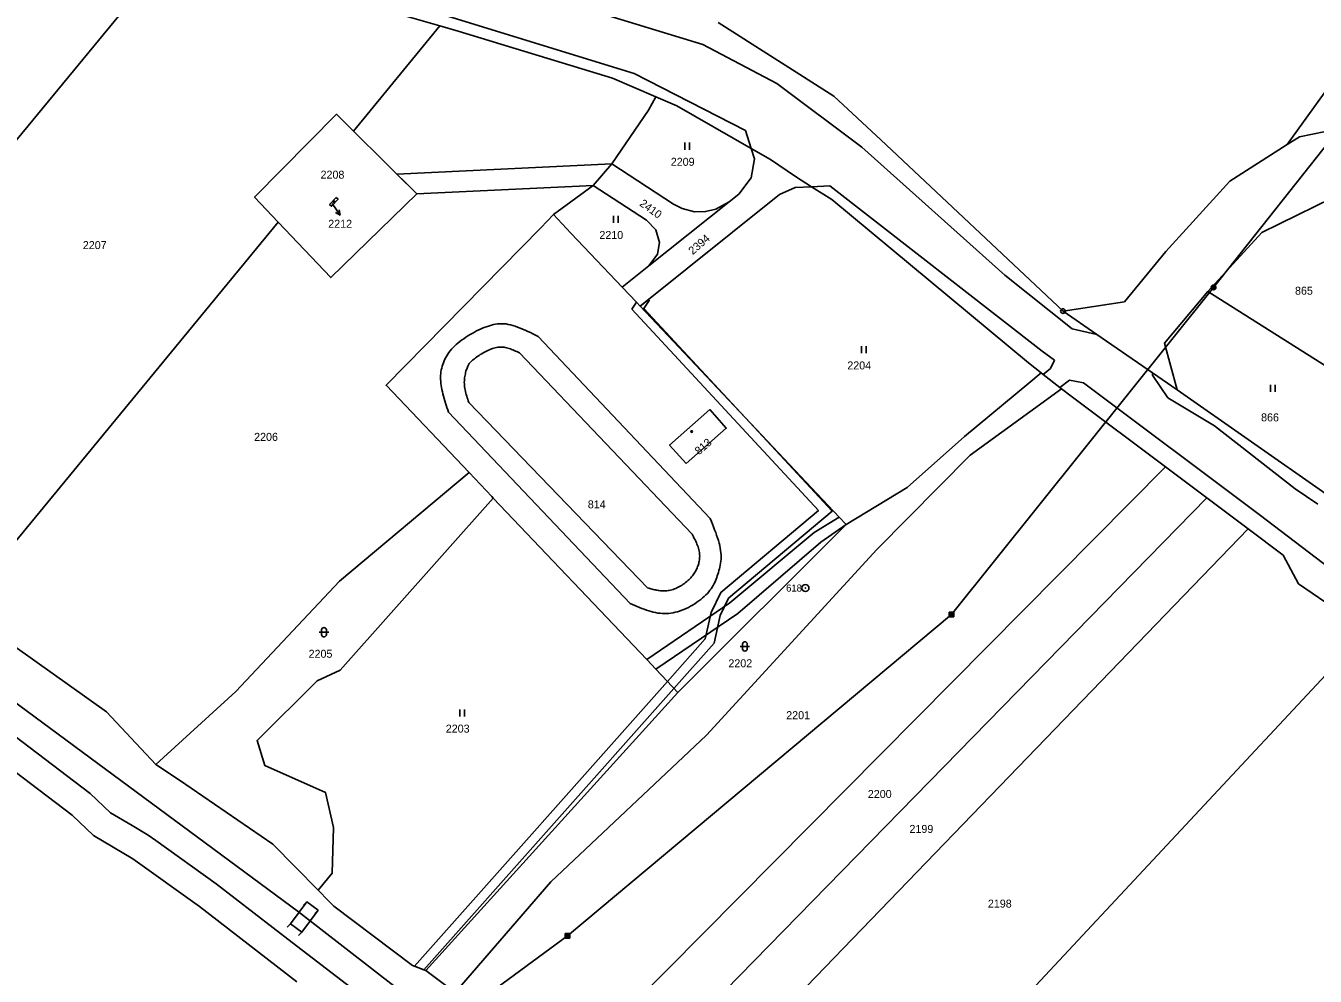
# Model space of a CAD drawing. Extents: x -504988 to -494607, y -1123820 to -1114018.
# Drawn here: x -503013.9 to -502739.9, y -1120138.9 to -1119937 of the extents above; entities that cross this region are included whole.
import ezdxf

# ---------------------------------------------------------------- set-up
doc = ezdxf.new("R2010")
doc.units = 0
for name, color, linetype in [('Hranice parcel', 7, 'Continuous'), ('Parcelní čísla', 7, 'Continuous'), ('Pop  PČ popisy', 7, 'Continuous'), ('Poz předměty', 7, 'Continuous'), ('Vnitřní kresba', 7, 'Continuous'), ('Věcná břemena k části', 7, 'Continuous'), ('Značky bodu BP', 7, 'Continuous'), ('Značky budov', 7, 'Continuous'), ('Značky kultur', 7, 'Continuous')]:
    doc.layers.add(name, color=color, linetype=linetype)

msp = doc.modelspace()

# ---------------------------------------------------------------- linework, layer by layer
at = {"layer": 'Hranice parcel'}
for p, q in [((-502981.99, -1119920.09), (-503071.71, -1120028.97)), ((-502925.9, -1119937.02), (-502944.29, -1119959.35)), ((-502893.32, -1119970.88), (-502889.37, -1119966.29)), ((-502901.73, -1119977.1), (-502893.32, -1119970.88)), ((-502864.44, -1119974.35), (-502881.5, -1119987.99)), ((-502960.25, -1119978.71), (-503027.8, -1120060.7)), ((-502887.17, -1119992.52), (-502881.5, -1119987.99)), ((-502762.74, -1119993.42), (-502729.28, -1120014.6)), ((-502769.23, -1120014.3), (-502737.68, -1120036.4)), ((-502771.74, -1120030.66), (-502900.98, -1120161.07)), ((-502762.94, -1120037.27), (-502771.74, -1120030.66)), ((-502762.94, -1120037.27), (-502892.07, -1120169.28)), ((-502754.13, -1120043.86), (-502883.26, -1120177.59)), ((-502728.91, -1120065.44), (-502856.99, -1120202.68)), ((-502875.32, -1120078.64), (-502928.87, -1120137.7)), ((-502928.87, -1120137.7), (-502922.69, -1120142.32))]:
    msp.add_line(p, q, dxfattribs=at)
for points in [[(-502745.87, -1119962.2), (-502726.12, -1119934.81), (-502725.62, -1119934.02), (-502724.98, -1119932.56), (-502724.62, -1119930.83), (-502724.51, -1119929.79), (-502723.39, -1119925.27), (-502721.48, -1119921.82), (-502719.31, -1119919.3), (-502694.18, -1119895.38), (-502669.78, -1119860.67), (-502662.28, -1119848.04), (-502656.73, -1119834.18), (-502653.41, -1119819.67), (-502652.38, -1119805.25), (-502653.63, -1119790.28), (-502657.45, -1119766.86), (-502661.64, -1119750.43), (-502684.82, -1119684.46), (-502688.04, -1119676.45), (-502695.69, -1119659.69), (-502696.84, -1119656.32)], [(-502925.9, -1119937.02), (-502942.28, -1119932.34), (-502981.04, -1119920.39), (-502981.99, -1119920.09)], [(-502866.76, -1119936.27), (-502842.16, -1119951.9), (-502832.22, -1119961.21), (-502793.5, -1119997.58)], [(-502880.05, -1119952.05), (-502889.25, -1119948.14), (-502921.99, -1119938.14), (-502925.9, -1119937.02)], [(-502889.37, -1119966.29), (-502881.58, -1119954.91), (-502880.05, -1119952.05)], [(-502859.74, -1119963.02), (-502875.54, -1119953.97), (-502880.05, -1119952.05)], [(-502960.25, -1119978.71), (-502965.29, -1119973.4), (-502947.89, -1119955.79), (-502944.29, -1119959.35)], [(-502734.16, -1119958.79), (-502734.97, -1119958.87), (-502743.27, -1119960.54), (-502745.87, -1119962.2)], [(-502944.29, -1119959.35), (-502930.79, -1119972.7), (-502949.08, -1119990.48), (-502960.25, -1119978.71)], [(-502864.44, -1119974.35), (-502862.41, -1119972.72), (-502859.78, -1119969.29), (-502859.04, -1119965.26), (-502859.74, -1119963.02)], [(-502859.74, -1119963.02), (-502855.64, -1119965.37), (-502850.31, -1119968.98), (-502846.92, -1119971.16)], [(-502745.87, -1119962.2), (-502758.03, -1119969.98), (-502771.67, -1119984.9), (-502780.46, -1119995.59), (-502793.5, -1119997.58)], [(-502889.37, -1119966.29), (-502876.25, -1119974.84), (-502874.45, -1119975.8), (-502871.8, -1119976.47), (-502869.43, -1119976.46), (-502867.25, -1119975.93), (-502864.44, -1119974.35)], [(-502881.5, -1119987.99), (-502879.69, -1119985.48), (-502879.26, -1119983.01), (-502880.04, -1119980.35), (-502881.97, -1119978.27), (-502893.32, -1119970.88)], [(-502846.92, -1119971.16), (-502850.4, -1119971.34), (-502853.76, -1119972.85), (-502883.38, -1119996.53)], [(-502798.12, -1120010.71), (-502800.84, -1120008.56), (-502842.65, -1119973.89), (-502846.92, -1119971.16)], [(-502762.74, -1119993.42), (-502751.25, -1119980.9), (-502736.26, -1119973.51), (-502722.85, -1119971.39)], [(-502947.95, -1119973.44), (-502947.53, -1119973.83), (-502948.91, -1119975.31), (-502949.33, -1119974.92), (-502947.95, -1119973.44)], [(-502901.73, -1119977.1), (-502904.47, -1119979.89), (-502937.32, -1120013.35), (-502919.69, -1120031.91)], [(-502887.17, -1119992.52), (-502888.43, -1119991.19), (-502898.05, -1119981.01), (-502901.73, -1119977.1)], [(-503153.21, -1119984.84), (-503117.67, -1120013.23), (-503061.37, -1120053.65), (-503000.19, -1120100.11), (-502995.88, -1120104.15), (-502991.31, -1120106.89), (-502987.9, -1120108.94), (-502986.29, -1120110.08), (-502973.43, -1120119.24), (-502957.29, -1120131.75), (-502934.18, -1120149.41), (-502874.44, -1120202.44), (-502827.95, -1120247.84), (-502804.36, -1120271.45), (-502786.5, -1120288.33), (-502769.05, -1120304.16), (-502747.51, -1120326.1), (-502711.16, -1120365.44)], [(-502883.38, -1119996.53), (-502884.16, -1119995.71), (-502887.17, -1119992.52)], [(-502769.23, -1120014.3), (-502771.91, -1120004.43), (-502762.74, -1119993.42)], [(-502839.58, -1120042.91), (-502841.06, -1120041.34), (-502883.38, -1119996.53)], [(-502793.5, -1119997.58), (-502786.3, -1120002.54), (-502774.49, -1120010.68), (-502769.23, -1120014.3)], [(-502798.12, -1120010.71), (-502800.75, -1120012.9), (-502814.41, -1120024.23), (-502826.58, -1120035.08), (-502839.58, -1120042.91)], [(-502793.79, -1120014.13), (-502794.15, -1120013.85), (-502797.68, -1120011.06), (-502798.12, -1120010.71)], [(-502793.79, -1120014.13), (-502813.21, -1120028.22), (-502833.09, -1120048.23), (-502869.28, -1120087.69), (-502902.3, -1120118.85), (-502922.69, -1120142.32)], [(-502771.74, -1120030.66), (-502791.73, -1120015.67), (-502793.79, -1120014.13)], [(-502873.56, -1120030), (-502865.05, -1120022.47), (-502868.57, -1120018.5), (-502877.08, -1120026.04), (-502873.56, -1120030)], [(-502919.69, -1120031.91), (-502947.21, -1120054.98), (-502969.27, -1120078.39), (-502986.24, -1120093.88)], [(-502919.69, -1120031.91), (-502914.9, -1120036.96), (-502914.56, -1120037.32)], [(-502914.56, -1120037.32), (-502947.1, -1120073.87), (-502952, -1120076.13), (-502964.76, -1120088.85), (-502963.11, -1120094.14), (-502950.2, -1120099.89), (-502948.54, -1120107.32), (-502948.77, -1120116.97), (-502951.78, -1120120.6)], [(-502914.56, -1120037.32), (-502881.96, -1120071.64), (-502880.04, -1120073.67), (-502875.32, -1120078.64)], [(-502754.13, -1120043.86), (-502754.73, -1120043.41), (-502759.54, -1120039.82), (-502762.94, -1120037.27)], [(-502875.32, -1120078.64), (-502872.77, -1120076.1), (-502842.23, -1120045.55), (-502839.58, -1120042.91)], [(-502728.91, -1120065.44), (-502743.49, -1120055.51), (-502746.69, -1120049.46), (-502754.13, -1120043.86)], [(-503027.8, -1120060.7), (-502996.74, -1120082.72), (-502986.24, -1120093.88)], [(-502956.27, -1120140.08), (-502977.01, -1120124.06), (-502991.18, -1120113.97), (-502999.52, -1120108.97), (-503004.07, -1120104.7), (-503023.32, -1120090.08)], [(-502986.24, -1120093.88), (-502981.23, -1120097.21), (-502961.37, -1120110.87), (-502951.78, -1120120.6)], [(-502951.78, -1120120.6), (-502951.51, -1120120.87), (-502949.82, -1120122.58), (-502948.43, -1120124), (-502931.7, -1120136.63), (-502928.87, -1120137.7)]]:
    msp.add_lwpolyline(points, dxfattribs=at)
at = {"layer": 'Pop  PČ popisy'}
for p, q in [((-502948.8, -1119974.7), (-502947.12, -1119977.19)), ((-502947.12, -1119977.19), (-502948.1, -1119976.64)), ((-502947.12, -1119977.19), (-502947.27, -1119976.08))]:
    msp.add_line(p, q, dxfattribs=at)
at = {"layer": 'Poz předměty'}
for p, q in [((-502719.6, -1119939.6), (-502761.52, -1119992.57)), ((-502761.52, -1119992.57), (-502817.21, -1120062.04)), ((-503042.38, -1120061.42), (-502955.94, -1120125.2)), ((-502817.21, -1120062.04), (-502898.76, -1120130.34)), ((-502817.71, -1120061.54), (-502816.71, -1120061.54)), ((-502817.71, -1120062.54), (-502817.71, -1120061.54)), ((-502817.71, -1120061.74), (-502816.71, -1120061.74)), ((-502817.71, -1120061.94), (-502816.71, -1120061.94)), ((-502817.71, -1120062.14), (-502816.71, -1120062.14)), ((-502817.71, -1120062.34), (-502816.71, -1120062.34)), ((-502817.71, -1120062.54), (-502816.71, -1120062.54)), ((-502817.51, -1120062.54), (-502817.51, -1120061.54)), ((-502817.31, -1120062.54), (-502817.31, -1120061.54)), ((-502817.11, -1120062.54), (-502817.11, -1120061.54)), ((-502816.91, -1120062.54), (-502816.91, -1120061.54)), ((-502816.71, -1120062.54), (-502816.71, -1120061.54)), ((-502955.94, -1120125.2), (-502924.74, -1120149.39)), ((-502898.76, -1120130.34), (-502942.5, -1120162.33)), ((-502899.26, -1120129.84), (-502898.26, -1120129.84)), ((-502899.26, -1120130.84), (-502899.26, -1120129.84)), ((-502899.26, -1120130.04), (-502898.26, -1120130.04)), ((-502899.26, -1120130.24), (-502898.26, -1120130.24)), ((-502899.26, -1120130.44), (-502898.26, -1120130.44)), ((-502899.26, -1120130.64), (-502898.26, -1120130.64)), ((-502899.26, -1120130.84), (-502898.26, -1120130.84)), ((-502899.06, -1120130.84), (-502899.06, -1120129.84)), ((-502898.86, -1120130.84), (-502898.86, -1120129.84)), ((-502898.66, -1120130.84), (-502898.66, -1120129.84)), ((-502898.46, -1120130.84), (-502898.46, -1120129.84)), ((-502898.26, -1120130.84), (-502898.26, -1120129.84))]:
    msp.add_line(p, q, dxfattribs=at)
for radius in [0.5, 0.4, 0.3, 0.2, 0.1]:
    msp.add_circle((-502761.52, -1119992.57), radius, dxfattribs=at)
at = {"layer": 'Vnitřní kresba'}
for p, q in [((-502884.59, -1119947.09), (-502935.96, -1119931.25)), ((-502891.62, -1119934.38), (-502870.01, -1119940.96)), ((-502870.01, -1119940.96), (-502854.29, -1119949.26)), ((-502860.93, -1119959.22), (-502884.59, -1119947.09)), ((-502854.29, -1119949.26), (-502836.28, -1119962.75)), ((-502859.74, -1119963.02), (-502860.93, -1119959.22)), ((-502836.28, -1119962.75), (-502805.85, -1119989.93)), ((-502843.01, -1119970.96), (-502846.92, -1119971.16)), ((-502797.91, -1120006.07), (-502843.01, -1119970.96)), ((-502805.85, -1119989.93), (-502791.52, -1120001.38)), ((-502791.52, -1120001.38), (-502786.3, -1120002.54)), ((-502905.01, -1120002.98), (-502868.46, -1120041.66)), ((-502909.02, -1120006.47), (-502872.3, -1120044.95)), ((-502795.31, -1120007.99), (-502797.91, -1120006.07)), ((-502795.31, -1120007.99), (-502796.14, -1120009.76)), ((-502796.14, -1120009.76), (-502797.68, -1120011.06)), ((-502774.48, -1120011.2), (-502774.49, -1120010.68)), ((-502792.13, -1120012.23), (-502794.15, -1120013.85)), ((-502789.11, -1120012.85), (-502792.13, -1120012.23)), ((-502751.84, -1120040.82), (-502789.11, -1120012.85)), ((-502771.26, -1120015.99), (-502774.48, -1120011.2)), ((-502771.26, -1120015.99), (-502761.31, -1120021.96)), ((-502885.45, -1120059.74), (-502924.07, -1120019.07)), ((-502881.79, -1120056.35), (-502919.78, -1120016.98)), ((-502761.31, -1120021.96), (-502744.14, -1120035.36)), ((-502744.14, -1120035.36), (-502739.32, -1120038.6)), ((-502723.08, -1120062.74), (-502751.84, -1120040.82)), ((-502841.06, -1120041.34), (-502846.38, -1120044.62)), ((-502844.96, -1120046.68), (-502839.58, -1120042.91)), ((-502846.38, -1120044.62), (-502864.29, -1120059.58)), ((-502862.58, -1120061.83), (-502844.96, -1120046.68)), ((-502864.29, -1120059.58), (-502881.96, -1120071.64)), ((-502880.04, -1120073.67), (-502862.58, -1120061.83)), ((-502957.63, -1120127.74), (-502954.18, -1120123.09)), ((-502954.89, -1120123.8), (-502954.18, -1120123.09)), ((-502954.18, -1120123.09), (-502951.78, -1120124.87)), ((-502955.23, -1120129.52), (-502951.78, -1120124.87)), ((-502952.49, -1120125.58), (-502951.78, -1120124.87)), ((-502958.34, -1120128.45), (-502957.63, -1120127.74)), ((-502957.63, -1120127.74), (-502955.23, -1120129.52)), ((-502955.94, -1120130.23), (-502955.23, -1120129.52))]:
    msp.add_line(p, q, dxfattribs=at)
for points in [[(-502924.07, -1120019.07), (-502924.23, -1120018.58), (-502924.4, -1120018.09), (-502924.56, -1120017.6), (-502924.71, -1120017.12), (-502924.86, -1120016.63), (-502925.01, -1120016.15), (-502925.14, -1120015.68), (-502925.27, -1120015.2), (-502925.38, -1120014.74), (-502925.48, -1120014.28), (-502925.57, -1120013.82), (-502925.64, -1120013.38), (-502925.7, -1120012.94), (-502925.73, -1120012.51), (-502925.75, -1120012.09), (-502925.76, -1120011.68), (-502925.74, -1120011.27), (-502925.72, -1120010.86), (-502925.67, -1120010.47), (-502925.6, -1120010.08), (-502925.52, -1120009.69), (-502925.42, -1120009.31), (-502925.3, -1120008.93), (-502925.17, -1120008.56), (-502925.02, -1120008.19), (-502924.85, -1120007.82), (-502924.66, -1120007.46), (-502924.45, -1120007.1), (-502924.23, -1120006.75), (-502923.98, -1120006.4), (-502923.72, -1120006.05), (-502923.43, -1120005.71), (-502923.12, -1120005.37), (-502922.8, -1120005.04), (-502922.45, -1120004.71), (-502922.08, -1120004.39), (-502921.69, -1120004.07), (-502921.28, -1120003.76), (-502920.85, -1120003.46), (-502920.42, -1120003.16), (-502919.96, -1120002.87), (-502919.5, -1120002.59), (-502919.04, -1120002.32), (-502918.56, -1120002.07), (-502918.09, -1120001.82), (-502917.63, -1120001.6), (-502917.16, -1120001.38), (-502916.7, -1120001.18), (-502916.25, -1120001), (-502915.81, -1120000.83), (-502915.37, -1120000.69), (-502914.94, -1120000.56), (-502914.51, -1120000.45), (-502914.08, -1120000.37), (-502913.64, -1120000.31), (-502913.2, -1120000.28), (-502912.76, -1120000.27), (-502912.31, -1120000.29), (-502911.85, -1120000.33), (-502911.38, -1120000.41), (-502910.9, -1120000.52), (-502910.4, -1120000.65), (-502909.89, -1120000.81), (-502909.38, -1120000.99), (-502908.85, -1120001.2), (-502908.32, -1120001.42), (-502907.78, -1120001.66), (-502907.23, -1120001.91), (-502906.68, -1120002.17), (-502906.13, -1120002.43), (-502905.57, -1120002.71), (-502905.01, -1120002.98)], [(-502919.78, -1120016.98), (-502919.89, -1120016.65), (-502919.99, -1120016.32), (-502920.1, -1120015.99), (-502920.2, -1120015.66), (-502920.29, -1120015.33), (-502920.38, -1120015), (-502920.46, -1120014.68), (-502920.53, -1120014.35), (-502920.59, -1120014.02), (-502920.64, -1120013.7), (-502920.68, -1120013.37), (-502920.7, -1120013.05), (-502920.71, -1120012.73), (-502920.7, -1120012.41), (-502920.68, -1120012.1), (-502920.65, -1120011.79), (-502920.6, -1120011.49), (-502920.55, -1120011.19), (-502920.49, -1120010.91), (-502920.43, -1120010.64), (-502920.36, -1120010.38), (-502920.29, -1120010.13), (-502920.21, -1120009.9), (-502920.14, -1120009.69), (-502920.07, -1120009.5), (-502919.99, -1120009.31), (-502919.92, -1120009.15), (-502919.83, -1120009), (-502919.74, -1120008.85), (-502919.65, -1120008.71), (-502919.54, -1120008.58), (-502919.42, -1120008.44), (-502919.29, -1120008.31), (-502919.14, -1120008.17), (-502918.98, -1120008.03), (-502918.79, -1120007.88), (-502918.58, -1120007.72), (-502918.36, -1120007.55), (-502918.11, -1120007.38), (-502917.86, -1120007.2), (-502917.59, -1120007.02), (-502917.31, -1120006.84), (-502917.02, -1120006.66), (-502916.73, -1120006.48), (-502916.43, -1120006.31), (-502916.13, -1120006.15), (-502915.83, -1120006), (-502915.54, -1120005.86), (-502915.25, -1120005.73), (-502914.97, -1120005.62), (-502914.69, -1120005.52), (-502914.42, -1120005.44), (-502914.14, -1120005.37), (-502913.87, -1120005.31), (-502913.61, -1120005.27), (-502913.34, -1120005.24), (-502913.07, -1120005.23), (-502912.81, -1120005.23), (-502912.54, -1120005.25), (-502912.28, -1120005.28), (-502912.01, -1120005.33), (-502911.74, -1120005.39), (-502911.48, -1120005.46), (-502911.21, -1120005.54), (-502910.93, -1120005.64), (-502910.66, -1120005.74), (-502910.39, -1120005.85), (-502910.12, -1120005.97), (-502909.84, -1120006.09), (-502909.57, -1120006.21), (-502909.29, -1120006.34), (-502909.02, -1120006.47)], [(-502868.46, -1120041.66), (-502868.22, -1120042.26), (-502867.98, -1120042.86), (-502867.75, -1120043.45), (-502867.52, -1120044.04), (-502867.3, -1120044.63), (-502867.1, -1120045.21), (-502866.91, -1120045.78), (-502866.73, -1120046.34), (-502866.58, -1120046.89), (-502866.45, -1120047.42), (-502866.33, -1120047.95), (-502866.25, -1120048.45), (-502866.19, -1120048.94), (-502866.16, -1120049.41), (-502866.15, -1120049.87), (-502866.17, -1120050.31), (-502866.2, -1120050.75), (-502866.26, -1120051.16), (-502866.33, -1120051.57), (-502866.41, -1120051.97), (-502866.5, -1120052.35), (-502866.6, -1120052.73), (-502866.72, -1120053.11), (-502866.83, -1120053.47), (-502866.95, -1120053.83), (-502867.08, -1120054.19), (-502867.21, -1120054.54), (-502867.35, -1120054.88), (-502867.5, -1120055.23), (-502867.67, -1120055.57), (-502867.85, -1120055.9), (-502868.05, -1120056.24), (-502868.27, -1120056.57), (-502868.51, -1120056.9), (-502868.78, -1120057.23), (-502869.07, -1120057.56), (-502869.39, -1120057.89), (-502869.73, -1120058.22), (-502870.1, -1120058.54), (-502870.49, -1120058.85), (-502870.9, -1120059.17), (-502871.32, -1120059.46), (-502871.75, -1120059.75), (-502872.2, -1120060.03), (-502872.65, -1120060.29), (-502873.11, -1120060.53), (-502873.58, -1120060.76), (-502874.04, -1120060.97), (-502874.5, -1120061.16), (-502874.97, -1120061.32), (-502875.42, -1120061.46), (-502875.88, -1120061.58), (-502876.35, -1120061.68), (-502876.8, -1120061.75), (-502877.26, -1120061.81), (-502877.73, -1120061.84), (-502878.19, -1120061.84), (-502878.66, -1120061.83), (-502879.13, -1120061.79), (-502879.6, -1120061.73), (-502880.07, -1120061.65), (-502880.56, -1120061.54), (-502881.04, -1120061.42), (-502881.52, -1120061.27), (-502882.01, -1120061.11), (-502882.49, -1120060.94), (-502882.98, -1120060.76), (-502883.48, -1120060.57), (-502883.97, -1120060.37), (-502884.46, -1120060.16), (-502884.96, -1120059.95), (-502885.45, -1120059.74)], [(-502872.3, -1120044.95), (-502872.14, -1120045.26), (-502871.99, -1120045.57), (-502871.84, -1120045.88), (-502871.69, -1120046.19), (-502871.54, -1120046.5), (-502871.41, -1120046.8), (-502871.28, -1120047.1), (-502871.16, -1120047.41), (-502871.05, -1120047.7), (-502870.96, -1120047.99), (-502870.88, -1120048.29), (-502870.81, -1120048.57), (-502870.76, -1120048.85), (-502870.73, -1120049.13), (-502870.71, -1120049.4), (-502870.7, -1120049.67), (-502870.71, -1120049.93), (-502870.73, -1120050.19), (-502870.76, -1120050.44), (-502870.8, -1120050.69), (-502870.85, -1120050.94), (-502870.91, -1120051.18), (-502870.98, -1120051.42), (-502871.05, -1120051.65), (-502871.13, -1120051.88), (-502871.22, -1120052.11), (-502871.31, -1120052.33), (-502871.42, -1120052.55), (-502871.53, -1120052.77), (-502871.65, -1120052.98), (-502871.78, -1120053.19), (-502871.92, -1120053.41), (-502872.07, -1120053.62), (-502872.23, -1120053.82), (-502872.41, -1120054.03), (-502872.59, -1120054.24), (-502872.79, -1120054.45), (-502873, -1120054.65), (-502873.22, -1120054.86), (-502873.45, -1120055.05), (-502873.69, -1120055.25), (-502873.93, -1120055.44), (-502874.19, -1120055.62), (-502874.45, -1120055.8), (-502874.71, -1120055.97), (-502874.98, -1120056.12), (-502875.25, -1120056.27), (-502875.52, -1120056.4), (-502875.79, -1120056.52), (-502876.07, -1120056.63), (-502876.34, -1120056.72), (-502876.61, -1120056.8), (-502876.89, -1120056.87), (-502877.16, -1120056.93), (-502877.42, -1120056.97), (-502877.7, -1120057.01), (-502877.97, -1120057.03), (-502878.23, -1120057.04), (-502878.5, -1120057.04), (-502878.76, -1120057.03), (-502879.02, -1120057.01), (-502879.28, -1120056.98), (-502879.54, -1120056.94), (-502879.79, -1120056.9), (-502880.04, -1120056.84), (-502880.3, -1120056.78), (-502880.55, -1120056.72), (-502880.8, -1120056.65), (-502881.05, -1120056.58), (-502881.29, -1120056.5), (-502881.54, -1120056.43), (-502881.79, -1120056.35)]]:
    msp.add_lwpolyline(points, dxfattribs=at)
at = {"layer": 'Věcná břemena k části'}
for points in [[(-502889.37, -1119966.29), (-502935.03, -1119968.51), (-502930.79, -1119972.7), (-502893.32, -1119970.88)], [(-502885.11, -1119997.2), (-502845.46, -1120039.94), (-502866.23, -1120057.35), (-502868.25, -1120061.62), (-502869.5, -1120067.22), (-502877.55, -1120076.29), (-502931.3, -1120136.78), (-502929.3, -1120137.54), (-502876.17, -1120077.74), (-502867.65, -1120068.16), (-502866.35, -1120062.27), (-502864.61, -1120058.61), (-502842.56, -1120040.12), (-502861.99, -1120019.18), (-502882.56, -1119997.01), (-502881.43, -1119995.34), (-502881.68, -1119995.17), (-502883.38, -1119996.53), (-502884.16, -1119995.71)]]:
    msp.add_lwpolyline(points, close=True, dxfattribs=at)
at = {"layer": 'Značky bodu BP'}
for centre, radius in [((-502793.5, -1119997.58), 0.5), ((-502793.5, -1119997.58), 0.0303), ((-502848.23, -1120056.43), 0.75), ((-502848.23, -1120056.43), 0.03)]:
    msp.add_circle(centre, radius, dxfattribs=at)
at = {"layer": 'Značky budov'}
for centre in [(-502948.39, -1119974.36), (-502872.42, -1120023.18)]:
    msp.add_circle(centre, 0.175, dxfattribs=at)
at = {"layer": 'Značky kultur'}
for p, q in [((-502873.84, -1119963.3), (-502873.84, -1119961.8)), ((-502872.84, -1119963.3), (-502872.84, -1119961.8)), ((-502889.02, -1119978.86), (-502889.02, -1119977.36)), ((-502888.02, -1119978.86), (-502888.02, -1119977.36)), ((-502836.34, -1120006.56), (-502836.34, -1120005.06)), ((-502835.34, -1120006.56), (-502835.34, -1120005.06)), ((-502749.39, -1120014.77), (-502749.39, -1120013.27)), ((-502748.39, -1120014.77), (-502748.39, -1120013.27)), ((-502951.03, -1120065.32), (-502951.03, -1120066.32)), ((-502950.03, -1120066.32), (-502950.03, -1120065.32)), ((-502951.53, -1120065.82), (-502949.53, -1120065.82)), ((-502861.59, -1120068.34), (-502861.59, -1120069.34)), ((-502860.59, -1120069.34), (-502860.59, -1120068.34)), ((-502862.09, -1120068.84), (-502860.09, -1120068.84)), ((-502921.65, -1120083.72), (-502921.65, -1120082.22)), ((-502920.65, -1120083.72), (-502920.65, -1120082.22))]:
    msp.add_line(p, q, dxfattribs=at)
for centre, start, end in [((-502950.53, -1120065.32), 0, 180), ((-502950.53, -1120066.32), 180, 359.9879), ((-502861.09, -1120068.34), 0, 180), ((-502861.09, -1120069.34), 180, 359.9879)]:
    msp.add_arc(centre, 0.5, start, end, dxfattribs=at)

# ---------------------------------------------------------------- texts
at = {"layer": 'Parcelní čísla'}
for s, p in [('2209', (-502876.84, -1119966.72)), ('2208', (-502951.26, -1119969.46)), ('2212', (-502949.62, -1119979.89)), ('2210', (-502892.01, -1119982.28)), ('2207', (-503001.77, -1119984.42)), ('865', (-502744.2, -1119994.11)), ('2204', (-502839.33, -1120009.98)), ('866', (-502751.41, -1120021.02)), ('2206', (-502965.37, -1120025.16)), ('814', (-502894.47, -1120039.49)), ('2205', (-502953.8, -1120071.24)), ('2202', (-502864.6, -1120073.26)), ('2201', (-502852.31, -1120084.29)), ('2203', (-502924.65, -1120087.14)), ('2200', (-502834.97, -1120101.03)), ('2199', (-502826.12, -1120108.45)), ('2198', (-502809.46, -1120124.32))]:
    msp.add_text(s, height=1.7, dxfattribs=at).set_placement(p)
for s, rotation, p in [('2410', 324, (-502883.62, -1119975.06)), ('2394', 41, (-502872.18, -1119985.72)), ('813', 41, (-502870.84, -1120028.24))]:
    msp.add_text(s, height=1.7, rotation=rotation, dxfattribs=at).set_placement(p)
at = {"layer": 'Značky bodu BP'}
msp.add_text('618', height=1.5, dxfattribs=at).set_placement((-502852.33, -1120057.18))

doc.saveas('drawing.dxf')
